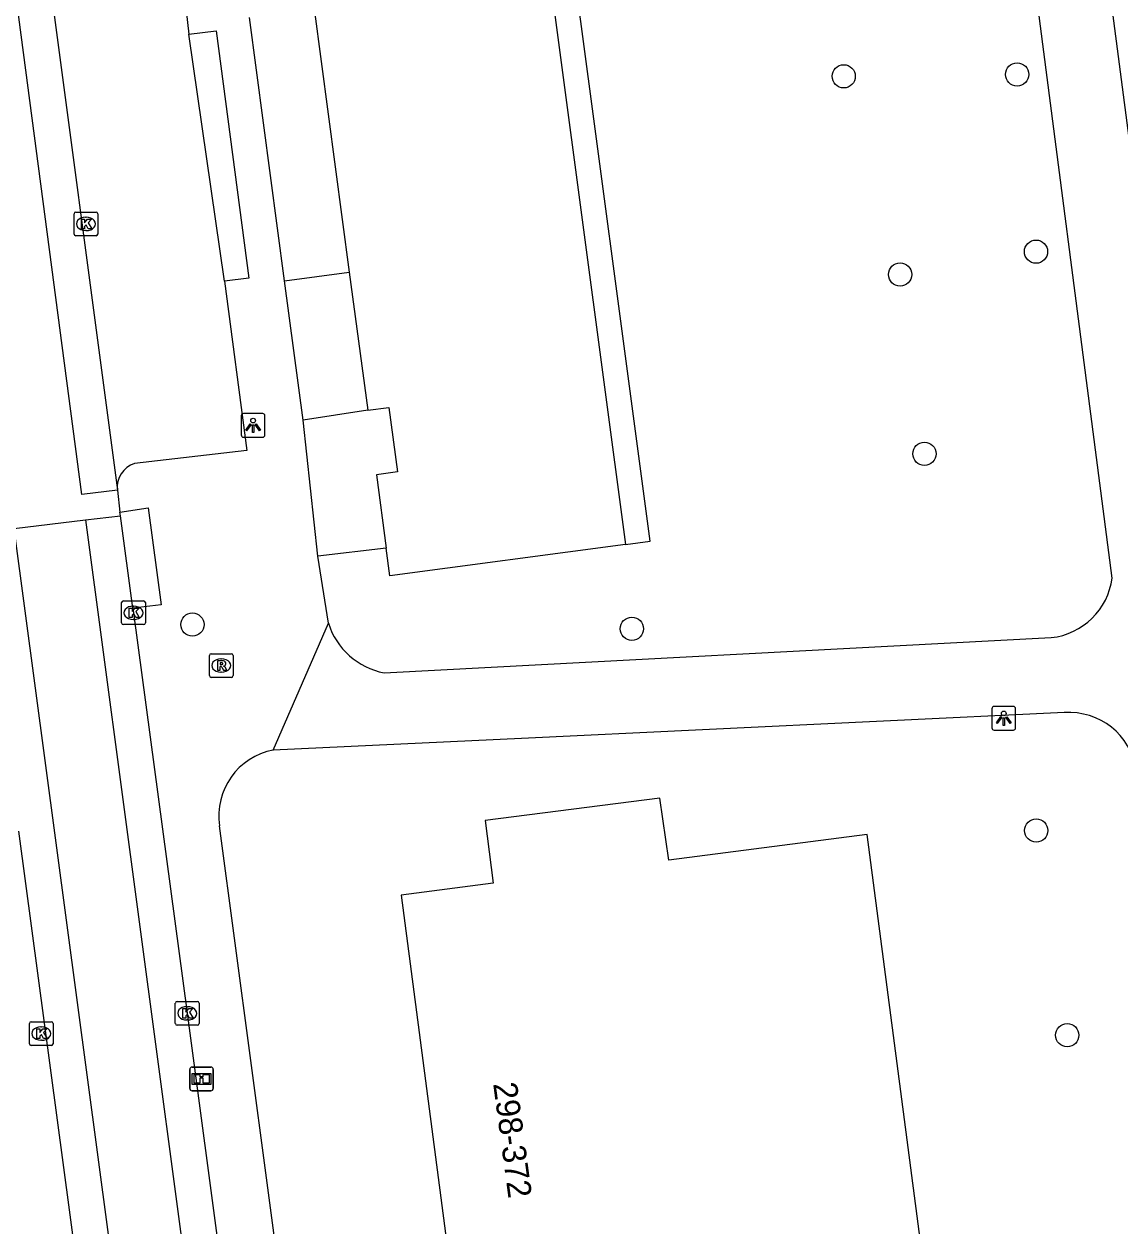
# Model space of a CAD drawing. Extents: x 160557 to 161245, y 385330 to 386505.
# Drawn here: x 161097.3 to 161143.5, y 385813.3 to 385863.9 of the extents above; entities that cross this region are included whole.
import ezdxf

# ---------------------------------------------------------------- set-up
doc = ezdxf.new("R2010")
doc.units = 0
for name, color, linetype in [('IMGEO_Boom', 7, 'Continuous'), ('IMGEO_Informatiebord', 7, 'Continuous'), ('IMGEO_Kolk', 7, 'Continuous'), ('IMGEO_Lichtpunt', 7, 'Continuous'), ('IMGEO_Pand', 7, 'Continuous'), ('IMGEO_Pand_nummerreeks', 7, 'Continuous'), ('IMGEO_Rijbaan_lokaal_gesloten', 7, 'Continuous'), ('IMGEO_Rijbaan_lokaal_open', 7, 'Continuous'), ('IMGEO_Rioolput', 7, 'Continuous'), ('IMGEO_Voetpad_open', 7, 'Continuous')]:
    doc.layers.add(name, color=color, linetype=linetype)

msp = doc.modelspace()

# ---------------------------------------------------------------- linework, layer by layer
at = {"layer": 'IMGEO_Boom'}
for centre in [(161139.168, 385861.821), (161131.863, 385861.74), (161139.963, 385854.353), (161134.239, 385853.391), (161135.264, 385845.837), (161104.431, 385838.641), (161122.94, 385838.467), (161139.973, 385829.965), (161141.278, 385821.343)]:
    msp.add_circle(centre, 0.489, dxfattribs=at)
at = {"layer": 'IMGEO_Informatiebord'}
for p, q in [((161104.319, 385819.102), (161104.319, 385819.902)), ((161104.319, 385819.902), (161104.319, 385819.102)), ((161104.419, 385820.002), (161105.209, 385820.002)), ((161105.209, 385820.002), (161104.419, 385820.002)), ((161105.309, 385819.902), (161105.309, 385819.102)), ((161105.309, 385819.102), (161105.309, 385819.902)), ((161105.209, 385819.002), (161104.419, 385819.002)), ((161104.419, 385819.002), (161105.209, 385819.002))]:
    msp.add_line(p, q, dxfattribs=at)
for points in [[(161104.42, 385819.734), (161105.208, 385819.734), (161105.208, 385819.27), (161104.42, 385819.27), (161104.42, 385819.734)], [(161104.485, 385819.669), (161104.485, 385819.335), (161104.76, 385819.335), (161104.761, 385819.548), (161104.865, 385819.549), (161104.866, 385819.335), (161105.143, 385819.335), (161105.143, 385819.669), (161104.867, 385819.669), (161104.867, 385819.589), (161104.761, 385819.589), (161104.761, 385819.669), (161104.485, 385819.669)]]:
    msp.add_lwpolyline(points, dxfattribs=at)
for centre, start, end in [((161104.419, 385819.902), 90, 180), ((161104.419, 385819.902), 90, 180), ((161105.209, 385819.902), 0, 90), ((161105.209, 385819.902), 360, 90), ((161104.419, 385819.102), 180, 270), ((161104.419, 385819.102), 180, 270), ((161105.209, 385819.102), 270, 0), ((161105.209, 385819.102), 270, 0)]:
    msp.add_arc(centre, 0.1, start, end, dxfattribs=at)
at = {"layer": 'IMGEO_Kolk'}
for p, q in [((161099.442, 385855.095), (161099.442, 385855.947)), ((161099.517, 385856.021), (161100.369, 385856.021)), ((161099.93, 385855.801), (161099.955, 385855.801)), ((161100.443, 385855.947), (161100.443, 385855.095)), ((161099.953, 385855.241), (161099.928, 385855.241)), ((161100.369, 385855.021), (161099.517, 385855.021)), ((161101.448, 385838.714), (161101.448, 385839.566)), ((161101.523, 385839.64), (161102.375, 385839.64)), ((161102.449, 385839.566), (161102.449, 385838.714)), ((161101.936, 385839.42), (161101.961, 385839.42)), ((161102.375, 385838.64), (161101.523, 385838.64)), ((161101.959, 385838.86), (161101.934, 385838.86)), ((161103.71, 385821.838), (161103.71, 385822.69)), ((161103.785, 385822.764), (161104.637, 385822.764)), ((161104.198, 385822.544), (161104.223, 385822.544)), ((161104.711, 385822.69), (161104.711, 385821.838)), ((161097.561, 385820.984), (161097.561, 385821.836)), ((161097.636, 385821.91), (161098.488, 385821.91)), ((161098.562, 385821.836), (161098.562, 385820.984)), ((161104.221, 385821.984), (161104.196, 385821.984)), ((161098.049, 385821.69), (161098.074, 385821.69)), ((161104.637, 385821.764), (161103.785, 385821.764)), ((161098.488, 385820.91), (161097.636, 385820.91)), ((161098.072, 385821.13), (161098.047, 385821.13))]:
    msp.add_line(p, q, dxfattribs=at)
for points in [[(161099.442, 385855.095), (161099.442, 385855.947)], [(161099.517, 385856.021), (161100.369, 385856.021)], [(161099.763, 385855.721), (161099.886, 385855.721), (161099.886, 385855.57), (161100.016, 385855.721), (161100.18, 385855.721), (161100.034, 385855.57), (161100.187, 385855.321), (161100.035, 385855.321), (161099.95, 385855.485), (161099.886, 385855.418), (161099.886, 385855.321), (161099.763, 385855.321), (161099.763, 385855.721)], [(161100.443, 385855.947), (161100.443, 385855.095)], [(161100.369, 385855.021), (161099.517, 385855.021)], [(161101.448, 385838.714), (161101.448, 385839.566)], [(161101.523, 385839.64), (161102.375, 385839.64)], [(161102.449, 385839.566), (161102.449, 385838.714)], [(161101.769, 385839.34), (161101.892, 385839.34), (161101.892, 385839.189), (161102.022, 385839.34), (161102.186, 385839.34), (161102.04, 385839.189), (161102.193, 385838.94), (161102.041, 385838.94), (161101.956, 385839.104), (161101.892, 385839.037), (161101.892, 385838.94), (161101.769, 385838.94), (161101.769, 385839.34)], [(161102.375, 385838.64), (161101.523, 385838.64)], [(161103.71, 385821.838), (161103.71, 385822.69)], [(161103.785, 385822.764), (161104.637, 385822.764)], [(161104.031, 385822.464), (161104.154, 385822.464), (161104.154, 385822.313), (161104.284, 385822.464), (161104.448, 385822.464), (161104.302, 385822.313), (161104.455, 385822.064), (161104.303, 385822.064), (161104.218, 385822.228), (161104.154, 385822.161), (161104.154, 385822.064), (161104.031, 385822.064), (161104.031, 385822.464)], [(161104.711, 385822.69), (161104.711, 385821.838)], [(161097.561, 385820.984), (161097.561, 385821.836)], [(161097.636, 385821.91), (161098.488, 385821.91)], [(161098.562, 385821.836), (161098.562, 385820.984)], [(161097.882, 385821.61), (161098.005, 385821.61), (161098.005, 385821.459), (161098.135, 385821.61), (161098.299, 385821.61), (161098.153, 385821.459), (161098.306, 385821.21), (161098.154, 385821.21), (161098.069, 385821.374), (161098.005, 385821.307), (161098.005, 385821.21), (161097.882, 385821.21), (161097.882, 385821.61)], [(161104.637, 385821.764), (161103.785, 385821.764)], [(161098.488, 385820.91), (161097.636, 385820.91)]]:
    msp.add_lwpolyline(points, dxfattribs=at)
for centre, start, end in [((161099.519, 385855.945), 91.552, 178.448), ((161099.519, 385855.945), 91.552, 178.448), ((161100.367, 385855.945), 1.552, 88.448), ((161100.367, 385855.945), 1.552, 88.448), ((161099.519, 385855.097), 181.552, 268.448), ((161099.519, 385855.097), 181.552, 268.448), ((161100.367, 385855.097), 271.552, 358.448), ((161100.367, 385855.097), 271.552, 358.448), ((161101.525, 385839.564), 91.552, 178.448), ((161101.525, 385839.564), 91.552, 178.448), ((161102.373, 385839.564), 1.552, 88.448), ((161102.373, 385839.564), 1.552, 88.448), ((161101.525, 385838.716), 181.552, 268.448), ((161101.525, 385838.716), 181.552, 268.448), ((161102.373, 385838.716), 271.552, 358.448), ((161102.373, 385838.716), 271.552, 358.448), ((161103.787, 385822.688), 91.552, 178.448), ((161103.787, 385822.688), 91.552, 178.448), ((161104.635, 385822.688), 1.552, 88.448), ((161104.635, 385822.688), 1.552, 88.448), ((161097.638, 385821.834), 91.552, 178.448), ((161097.638, 385821.834), 91.552, 178.448), ((161098.486, 385821.834), 1.552, 88.448), ((161098.486, 385821.834), 1.552, 88.448), ((161103.787, 385821.84), 181.552, 268.448), ((161103.787, 385821.84), 181.552, 268.448), ((161104.635, 385821.84), 271.552, 358.448), ((161104.635, 385821.84), 271.552, 358.448), ((161097.638, 385820.986), 181.552, 268.448), ((161097.638, 385820.986), 181.552, 268.448), ((161098.486, 385820.986), 271.552, 358.448), ((161098.486, 385820.986), 271.552, 358.448)]:
    msp.add_arc(centre, 0.0765, start, end, dxfattribs=at)
for centre, major_axis, ratio, start_param, end_param in [((161099.929, 385855.521), (-0.387, 0.002), 0.722429, 4.712389, 7.853982), ((161099.954, 385855.521), (-0.39, 0.002), 0.717154, 1.570796, 4.712389), ((161101.935, 385839.14), (-0.387, 0.002), 0.722429, 4.712389, 7.853982), ((161101.96, 385839.14), (-0.39, 0.002), 0.717154, 1.570796, 4.712389), ((161104.197, 385822.264), (-0.387, 0.002), 0.722429, 4.712389, 7.853982), ((161104.222, 385822.264), (-0.39, 0.002), 0.717154, 1.570796, 4.712389), ((161098.048, 385821.41), (-0.387, 0.002), 0.722429, 4.712389, 7.853982), ((161098.073, 385821.41), (-0.39, 0.002), 0.717154, 1.570796, 4.712389)]:
    msp.add_ellipse(centre, major_axis=major_axis, ratio=ratio, start_param=start_param, end_param=end_param, dxfattribs=at)
at = {"layer": 'IMGEO_Lichtpunt'}
for p, q in [((161106.487, 385847.437), (161106.487, 385846.63)), ((161106.487, 385847.437), (161106.487, 385846.63)), ((161107.389, 385847.532), (161106.581, 385847.532)), ((161107.389, 385847.532), (161106.581, 385847.532)), ((161107.483, 385846.63), (161107.483, 385847.437)), ((161107.483, 385846.63), (161107.483, 385847.437)), ((161106.581, 385846.536), (161107.389, 385846.536)), ((161106.581, 385846.536), (161107.389, 385846.536)), ((161138.106, 385835.099), (161138.106, 385834.292)), ((161138.106, 385835.099), (161138.106, 385834.292)), ((161139.008, 385835.194), (161138.2, 385835.194)), ((161139.008, 385835.194), (161138.2, 385835.194)), ((161139.102, 385834.292), (161139.102, 385835.099)), ((161139.102, 385834.292), (161139.102, 385835.099)), ((161138.2, 385834.198), (161139.008, 385834.198)), ((161138.2, 385834.198), (161139.008, 385834.198))]:
    msp.add_line(p, q, dxfattribs=at)
for points in [[(161106.861, 385847.101), (161106.9, 385847.073), (161106.712, 385846.811), (161106.674, 385846.838), (161106.861, 385847.101)], [(161107.073, 385847.073), (161107.111, 385847.1), (161107.298, 385846.838), (161107.259, 385846.81), (161107.073, 385847.073)], [(161106.963, 385847.053), (161107.01, 385847.053), (161107.01, 385846.731), (161106.963, 385846.731), (161106.963, 385847.053)], [(161138.48, 385834.763), (161138.519, 385834.735), (161138.331, 385834.473), (161138.293, 385834.5), (161138.48, 385834.763)], [(161138.582, 385834.715), (161138.629, 385834.715), (161138.629, 385834.393), (161138.582, 385834.393), (161138.582, 385834.715)], [(161138.692, 385834.735), (161138.73, 385834.762), (161138.917, 385834.5), (161138.878, 385834.472), (161138.692, 385834.735)]]:
    msp.add_lwpolyline(points, dxfattribs=at)
for centre in [(161106.986, 385847.235), (161138.605, 385834.897)]:
    msp.add_circle(centre, 0.0994, dxfattribs=at)
for centre, start, end in [((161106.581, 385847.437), 90, 180), ((161106.581, 385847.437), 90, 180), ((161107.389, 385847.437), 0, 90), ((161107.389, 385847.437), 0, 90), ((161106.581, 385846.63), 180, 270), ((161106.581, 385846.63), 180, 270), ((161107.389, 385846.63), 270, 0), ((161107.389, 385846.63), 270, 360), ((161138.2, 385835.099), 90, 180), ((161138.2, 385835.099), 90, 180), ((161139.008, 385835.099), 0, 90), ((161139.008, 385835.099), 0, 90), ((161138.2, 385834.292), 180, 270), ((161138.2, 385834.292), 180, 270), ((161139.008, 385834.292), 270, 0), ((161139.008, 385834.292), 270, 360)]:
    msp.add_arc(centre, 0.0946, start, end, dxfattribs=at)
at = {"layer": 'IMGEO_Pand'}
for points in [[(161098.088, 385950.557), (161108.009, 385951.88), (161122.665, 385842.019)], [(161109.558, 385864.577), (161111.038, 385853.491)], [(161111.038, 385853.491), (161111.814, 385847.674)], [(161111.814, 385847.674), (161112.705, 385847.793), (161113.068, 385845.071), (161112.186, 385844.953), (161112.591, 385841.865)], [(161122.665, 385842.019), (161112.744, 385840.696), (161112.591, 385841.865)], [(161124.339, 385799.127), (161138.794, 385800.962), (161137.524, 385810.46), (161135.427, 385810.18), (161132.855, 385829.793), (161124.495, 385828.714), (161124.12, 385831.334), (161116.76, 385830.384), (161117.093, 385827.746), (161113.225, 385827.247), (161115.311, 385811.271)]]:
    msp.add_lwpolyline(points, dxfattribs=at)
at = {"layer": 'IMGEO_Rijbaan_lokaal_gesloten'}
for points in [[(161101.269, 385844.311), (161099.778, 385844.122), (161095.943, 385873.076), (161097.379, 385873.281)], [(161098, 385868.872), (161101.269, 385844.311)]]:
    msp.add_lwpolyline(points, dxfattribs=at)
at = {"layer": 'IMGEO_Rijbaan_lokaal_open'}
for points in [[(161108.31, 385853.127), (161106.831, 385864.213)], [(161108.31, 385853.127), (161111.038, 385853.491)], [(161101.269, 385844.311), (161101.379, 385843.379)], [(161096.923, 385842.687), (161099.92, 385843.054)], [(161099.92, 385843.054), (161101.395, 385843.23)], [(161099.92, 385843.054), (161106.707, 385792.242)], [(161101.395, 385843.23), (161101.379, 385843.379)], [(161101.922, 385839.331), (161101.395, 385843.23)], [(161103.751, 385791.851), (161102.669, 385799.702), (161096.923, 385842.687)], [(161101.922, 385839.331), (161101.949, 385839.14), (161104.211, 385822.264), (161107.188, 385799.961), (161108.204, 385792.51)], [(161097.109, 385829.938), (161100.064, 385807.789)]]:
    msp.add_lwpolyline(points, dxfattribs=at)
at = {"layer": 'IMGEO_Rioolput'}
for p, q in [((161105.144, 385836.49), (161105.144, 385837.342)), ((161105.219, 385837.416), (161106.071, 385837.416)), ((161105.632, 385837.196), (161105.657, 385837.196)), ((161106.145, 385837.342), (161106.145, 385836.49)), ((161105.655, 385836.636), (161105.63, 385836.636)), ((161106.071, 385836.416), (161105.219, 385836.416))]:
    msp.add_line(p, q, dxfattribs=at)
for points in [[(161105.144, 385836.49), (161105.144, 385837.342)], [(161105.219, 385837.416), (161106.071, 385837.416)], [(161105.733, 385837.114), (161105.481, 385837.116), (161105.481, 385836.716)], [(161105.659, 385837.035), (161105.605, 385837.035), (161105.605, 385836.954)], [(161106.145, 385837.342), (161106.145, 385836.49)], [(161105.481, 385836.716), (161105.605, 385836.716), (161105.605, 385836.878), (161105.616, 385836.878)], [(161105.605, 385836.954), (161105.657, 385836.954)], [(161105.663, 385836.849), (161105.734, 385836.716), (161105.874, 385836.716), (161105.809, 385836.842)], [(161106.071, 385836.416), (161105.219, 385836.416)]]:
    msp.add_lwpolyline(points, dxfattribs=at)
for centre, radius, start, end in [((161105.221, 385837.34), 0.0765, 91.552, 178.448), ((161105.221, 385837.34), 0.0765, 91.552, 178.448), ((161105.665, 385836.939), 0.0964, 77.0061, 93.1865), ((161105.679, 385836.996), 0.0378, 276.6634, 79.6772), ((161105.732, 385837.004), 0.109, 350.3612, 89.416), ((161105.73, 385837.004), 0.112, 277.5842, 350.9817), ((161106.069, 385837.34), 0.0765, 1.552, 88.448), ((161106.069, 385837.34), 0.0765, 1.552, 88.448), ((161105.221, 385836.492), 0.0765, 181.552, 268.448), ((161105.221, 385836.492), 0.0765, 181.552, 268.448), ((161105.615, 385836.825), 0.0533, 26.0293, 88.6989), ((161105.641, 385837.143), 0.19, 274.7715, 282.9687), ((161105.714, 385836.789), 0.108, 29.5134, 73.7905), ((161106.069, 385836.492), 0.0765, 271.552, 358.448), ((161106.069, 385836.492), 0.0765, 271.552, 358.448)]:
    msp.add_arc(centre, radius, start, end, dxfattribs=at)
for centre, major_axis, ratio, start_param, end_param in [((161105.631, 385836.916), (-0.387, 0.002), 0.722429, 4.712389, 7.853982), ((161105.656, 385836.916), (-0.39, 0.002), 0.717154, 1.570796, 4.712389)]:
    msp.add_ellipse(centre, major_axis=major_axis, ratio=ratio, start_param=start_param, end_param=end_param, dxfattribs=at)
at = {"layer": 'IMGEO_Voetpad_open'}
for points in [[(161122.665, 385842.019), (161123.708, 385842.158), (161122.752, 385849.325), (161121.251, 385860.582), (161118.463, 385881.489), (161115.749, 385901.843), (161112.775, 385924.141), (161109.928, 385945.494), (161108.541, 385955.891), (161097.601, 385954.29)], [(161135.368, 385924.28), (161147.764, 385829.368), (161149.183, 385819.023), (161150.29, 385819.102)], [(161143.172, 385840.601), (161132.353, 385923.907)], [(161103.691, 385868.717), (161104.275, 385863.522)], [(161104.275, 385863.522), (161105.424, 385863.655), (161106.805, 385853.234), (161105.78, 385853.116)], [(161105.78, 385853.116), (161104.275, 385863.522)], [(161105.78, 385853.116), (161106.726, 385845.974), (161101.992, 385845.423)], [(161109.093, 385847.254), (161108.31, 385853.127)], [(161111.814, 385847.674), (161109.093, 385847.254)], [(161109.707, 385841.529), (161109.093, 385847.254)], [(161101.379, 385843.379), (161102.567, 385843.564), (161103.109, 385839.473), (161101.922, 385839.331)], [(161112.591, 385841.865), (161109.707, 385841.529)], [(161110.155, 385838.705), (161109.707, 385841.529)], [(161107.835, 385833.357), (161110.155, 385838.705)], [(161112.504, 385836.608), (161140.603, 385838.092)], [(161141.156, 385834.932), (161118.295, 385833.84), (161107.835, 385833.357)], [(161108.212, 385810.396), (161105.573, 385830.161)]]:
    msp.add_lwpolyline(points, dxfattribs=at)
for centre, radius, start, end in [((161102.286, 385844.44), 1.026, 106.6848, 187.253), ((161140.288, 385840.984), 2.909, 276.2122, 352.4339), ((161113.083, 385839.62), 3.067, 197.3629, 259.1253), ((161141.348, 385832.051), 2.888, 9.6777, 93.8166), ((161108.367, 385830.582), 2.826, 100.8573, 188.564)]:
    msp.add_arc(centre, radius, start, end, dxfattribs=at)

# ---------------------------------------------------------------- texts
at = {"layer": 'IMGEO_Pand_nummerreeks'}
msp.add_text('298-372', height=1, rotation=277.6087, dxfattribs=at).set_placement((161117.096, 385819.299))

doc.saveas('drawing.dxf')
